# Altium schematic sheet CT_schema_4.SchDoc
size 287 x 160 mm
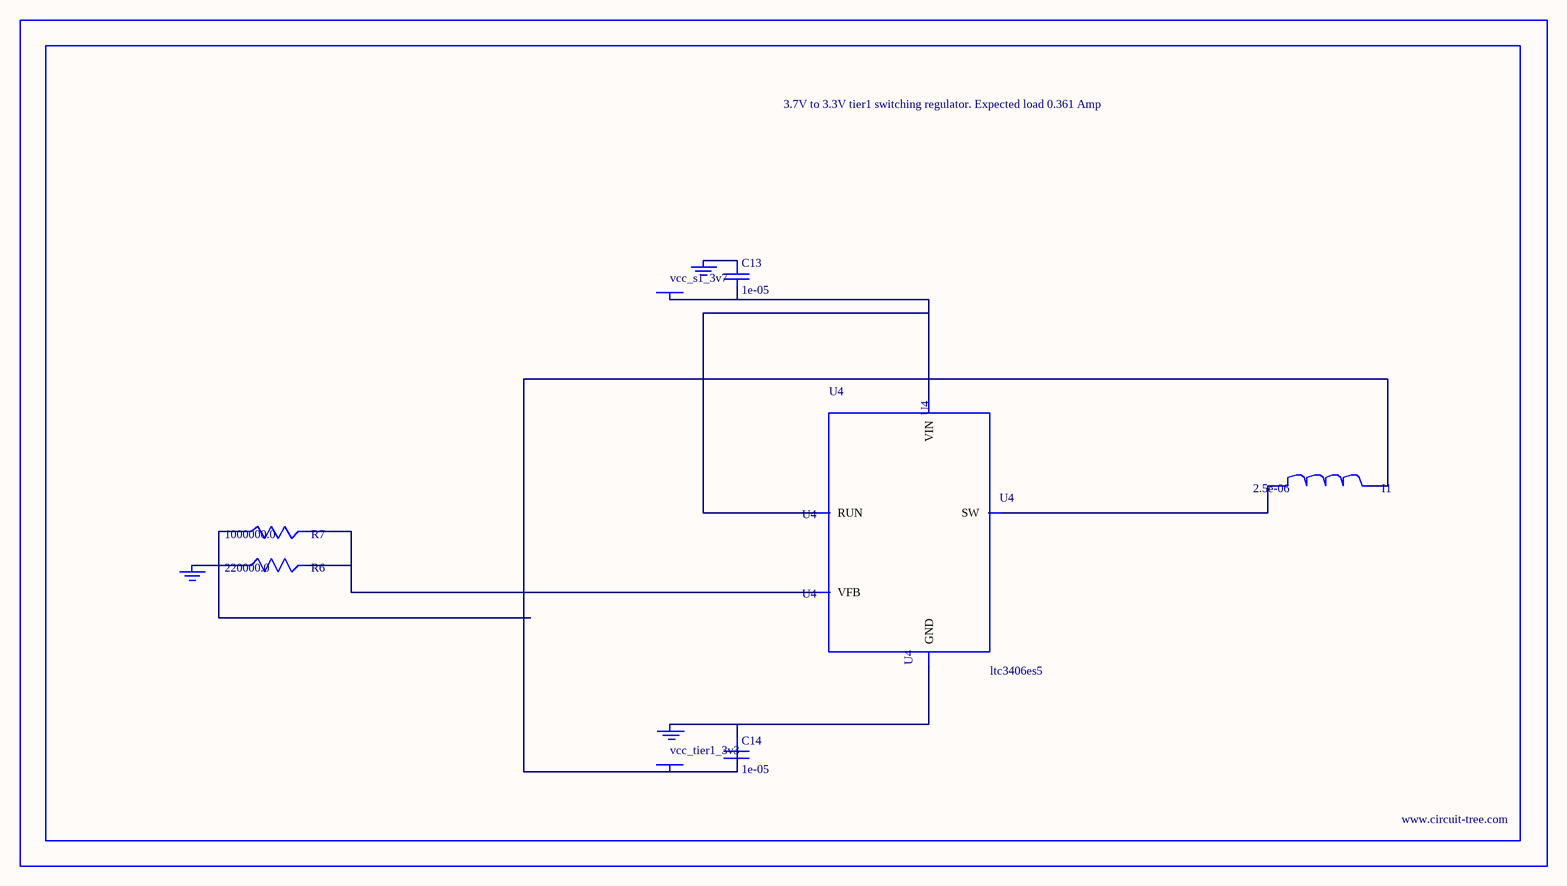
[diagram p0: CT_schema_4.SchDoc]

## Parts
BORDER3  (no value)
C13  1e-05  [C0805]
C14  1e-05  [C0805]
GND_INSTANCE_3_0  (no value)
GND_INSTANCE_3_1  (no value)
GND_INSTANCE_3_2  (no value)
I1  2.5e-06  [DR1040]
POWER_INSTANCE_3_0  vcc_tier1_3v3
POWER_INSTANCE_3_1  vcc_s1_3v7
R6  220000.0  [R0603]
R7  1000000.0  [R0603]
U4  ltc3406es5  [TSOT-23-5]

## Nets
NetC13_1: C13.1 GND_INSTANCE_3_1.0(GND)
NetC13_2: C13.2 POWER_INSTANCE_3_1.0(PWR) U4.1(RUN) U4.4(VIN)
NetC14_1: C14.1 GND_INSTANCE_3_0.0(GND) U4.2(GND)
NetC14_2: C14.2 I1.2 POWER_INSTANCE_3_0.0(PWR) R7.1
NetGND_INSTANCE_3_2_0: GND_INSTANCE_3_2.0(GND) R6.1
NetI1_1: I1.1 U4.3(SW)
NetR6_2: R6.2 R7.2 U4.5(VFB)

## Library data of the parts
BORDER3 = BORDER_PAGE3
C13 C14 = C0805C106K8RACTU
GND_INSTANCE_3_0-GND_INSTANCE_3_2 = GND
I1 = DR1040-2R5-R
POWER_INSTANCE_3_0 POWER_INSTANCE_3_1 = PWR
R6 = RC0603JR-07220KL
R7 = RC0603JR-071ML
